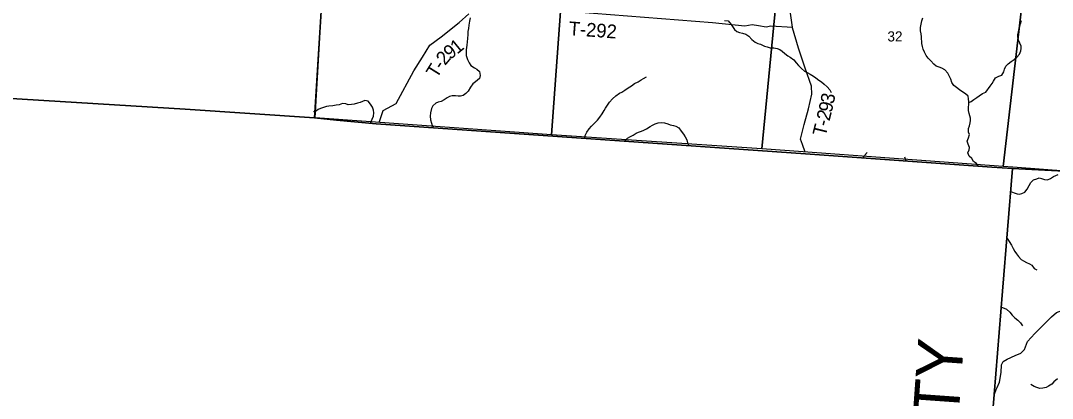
# Model space of a CAD drawing. Extents: x 1715311 to 2083412, y 146837 to 553079.
# Drawn here: x 1874751 to 1897277, y 339371 to 347616 of the extents above; entities that cross this region are included whole.
import ezdxf

# ---------------------------------------------------------------- set-up
doc = ezdxf.new("R2010")
doc.units = 0
for name, color, linetype in [('GM_X_Adjacent_County', 7, 'Continuous'), ('GM_X_Adjacent_County_Text', 7, 'Continuous'), ('GM_X_County', 7, 'Continuous'), ('GM_X_County_Road', 7, 'Continuous'), ('GM_X_Major_River', 7, 'Continuous'), ('GM_X_Minor_River', 7, 'Continuous'), ('GM_X_Section', 7, 'Continuous'), ('GM_X_Section_Text', 7, 'Continuous'), ('GM_X_Township', 7, 'Continuous'), ('GM_X_Township_Road', 7, 'Continuous'), ('GM_X_Township_Road_Text', 7, 'Continuous')]:
    doc.layers.add(name, color=color, linetype=linetype)

msp = doc.modelspace()

# ---------------------------------------------------------------- linework, layer by layer
at = {"layer": 'GM_X_Adjacent_County'}
for points in [[(1882647, 364366), (1882063, 357591), (1881945, 356213), (1881936, 356109), (1881811, 354649), (1881526, 351343), (1881415, 350049), (1881322, 347941), (1881166, 345493), (1878346, 345682), (1874430, 345924)], [(1874430, 345924), (1878346, 345682), (1881166, 345493), (1881644, 345443), (1882510, 345364), (1891886, 344709), (1895952, 344420), (1896407, 344385), (1896189, 341713), (1896008, 339458), (1895779, 336659)]]:
    msp.add_lwpolyline(points, dxfattribs=at)
at = {"layer": 'GM_X_County'}
msp.add_lwpolyline([(1895779, 336659), (1896008, 339458), (1896189, 341713), (1896407, 344385), (1895952, 344420), (1891886, 344709), (1882510, 345364), (1881644, 345443), (1881166, 345493), (1881322, 347941), (1881415, 350049), (1881526, 351343), (1881811, 354649), (1881936, 356109), (1881945, 356213), (1882063, 357591), (1882647, 364366)], dxfattribs=at)
at = {"layer": 'GM_X_County_Road'}
for points in [[(1896069, 339606), (1896121, 339723), (1896156, 339934), (1896165, 340102), (1896200, 340172), (1896288, 340225), (1896464, 340304), (1896587, 340357), (1896666, 340436), (1896737, 340612), (1896895, 340788), (1897071, 340963), (1897256, 341148), (1897370, 341245), (1897485, 341289), (1897810, 341298), (1898567, 341254), (1899198, 341237)], [(1895777, 336640), (1895779, 336659), (1896008, 339458), (1896011, 339465), (1896051, 339565), (1896068, 339605), (1896069, 339606)]]:
    msp.add_lwpolyline(points, dxfattribs=at)
at = {"layer": 'GM_X_Major_River'}
msp.add_lwpolyline([(1884565, 347678), (1884550, 347604), (1884538, 347514), (1884529, 347444), (1884518, 347376), (1884512, 347310), (1884505, 347226), (1884501, 347156), (1884494, 347084), (1884488, 347028), (1884477, 346976), (1884477, 346921), (1884480, 346853), (1884505, 346767), (1884541, 346693), (1884582, 346634), (1884658, 346584), (1884711, 346553), (1884771, 346505), (1884786, 346422), (1884770, 346350), (1884685, 346279), (1884621, 346235), (1884574, 346162), (1884522, 346078), (1884471, 346022), (1884409, 345981), (1884357, 345969), (1884305, 345970), (1884245, 345974), (1884175, 345973), (1884115, 345959), (1884065, 345932), (1884000, 345888), (1883934, 345851), (1883866, 345837), (1883816, 345816), (1883747, 345754), (1883721, 345698), (1883698, 345600), (1883692, 345528), (1883701, 345454), (1883718, 345380), (1883736, 345330), (1883758, 345292)], dxfattribs=at)
at = {"layer": 'GM_X_Minor_River'}
for points in [[(1890117, 347616), (1890197, 347610), (1890261, 347535), (1890309, 347469), (1890338, 347419), (1890390, 347379), (1890444, 347357), (1890514, 347340), (1890582, 347322), (1890652, 347274), (1890713, 347205), (1890785, 347147), (1890845, 347119), (1890907, 347099), (1890991, 347062), (1891051, 347044), (1891118, 347024), (1891194, 347020), (1891268, 347005), (1891326, 346987), (1891378, 346953), (1891436, 346899), (1891498, 346850), (1891549, 346820), (1891629, 346758), (1891681, 346696), (1891737, 346639), (1891796, 346569), (1891866, 346513), (1891922, 346483), (1891986, 346446), (1892058, 346406), (1892113, 346364), (1892175, 346316), (1892235, 346279), (1892297, 346229), (1892360, 346171), (1892416, 346103), (1892448, 346048)], [(1895662, 344441), (1895618, 344498), (1895552, 344542), (1895520, 344609), (1895461, 344659), (1895433, 344731), (1895461, 344797), (1895467, 344847), (1895438, 344921), (1895420, 344987), (1895442, 345057), (1895464, 345131), (1895445, 345183), (1895443, 345263), (1895467, 345321), (1895479, 345387), (1895489, 345437), (1895492, 345489), (1895460, 345590), (1895448, 345658), (1895448, 345724), (1895455, 345786), (1895455, 345844), (1895449, 345912), (1895435, 345964), (1895382, 346018), (1895320, 346058), (1895246, 346105), (1895180, 346153), (1895128, 346197), (1895085, 346267), (1895059, 346340), (1895033, 346400), (1894993, 346468), (1894930, 346540), (1894864, 346580), (1894806, 346599), (1894740, 346621), (1894688, 346669), (1894621, 346737), (1894563, 346800), (1894523, 346858), (1894484, 346930), (1894454, 346992), (1894442, 347052), (1894430, 347116), (1894419, 347261), (1894411, 347325), (1894401, 347395), (1894399, 347467), (1894412, 347537), (1894430, 347609), (1894448, 347675)], [(1895455, 345828), (1895507, 345854), (1895563, 345895), (1895631, 345939), (1895681, 345973), (1895751, 346025), (1895821, 346051), (1895922, 346182), (1895964, 346244), (1895994, 346298), (1896032, 346370), (1896110, 346406), (1896170, 346424), (1896215, 346498), (1896235, 346554), (1896261, 346620), (1896313, 346675), (1896377, 346721), (1896441, 346771), (1896498, 346821), (1896556, 346887), (1896588, 346957), (1896598, 347009), (1896594, 347059), (1896563, 347125), (1896535, 347191), (1896521, 347259), (1896525, 347315), (1896535, 347365), (1896548, 347415), (1896568, 347487), (1896582, 347547), (1896600, 347619)], [(1887072, 345056), (1887079, 345111), (1887113, 345180), (1887167, 345256), (1887215, 345314), (1887280, 345380), (1887342, 345446), (1887398, 345510), (1887446, 345580), (1887488, 345654), (1887519, 345705), (1887561, 345773), (1887607, 345837), (1887671, 345909), (1887747, 345975), (1887827, 346031), (1887878, 346058), (1887944, 346098), (1888018, 346150), (1888090, 346194), (1888156, 346246), (1888230, 346281), (1888296, 346325), (1888348, 346351), (1888418, 346389)], [(1882397, 345390), (1882426, 345467), (1882452, 345533), (1882460, 345605), (1882452, 345659), (1882431, 345725), (1882393, 345795), (1882335, 345856), (1882267, 345870), (1882213, 345850), (1882161, 345832), (1882103, 345812), (1882031, 345795), (1881977, 345785), (1881905, 345779), (1881849, 345797), (1881781, 345805), (1881707, 345778), (1881639, 345774), (1881565, 345756), (1881483, 345746), (1881429, 345743), (1881301, 345699), (1881249, 345677), (1881185, 345629), (1881148, 345623)], [(1887941, 344993), (1888000, 345049), (1888054, 345081), (1888126, 345115), (1888192, 345159), (1888242, 345178), (1888308, 345204), (1888358, 345224), (1888414, 345254), (1888494, 345302), (1888548, 345334), (1888601, 345365), (1888671, 345383), (1888740, 345393), (1888810, 345387), (1888880, 345364), (1888934, 345344), (1889002, 345324), (1889054, 345310), (1889124, 345276), (1889169, 345205), (1889221, 345135), (1889257, 345083), (1889293, 345011), (1889312, 344947), (1889343, 344893)], [(1893143, 344621), (1893176, 344675), (1893233, 344739)], [(1894082, 344554), (1894054, 344634)], [(1896370, 343883), (1896439, 343859), (1896509, 343833), (1896561, 343828), (1896611, 343842), (1896673, 343874), (1896723, 343940), (1896767, 344016), (1896804, 344082), (1896868, 344142), (1896936, 344165), (1896988, 344181), (1897042, 344169), (1897108, 344145), (1897170, 344143), (1897234, 344172), (1897300, 344216), (1897400, 344255)], [(1896287, 342861), (1896331, 342793), (1896385, 342714), (1896419, 342644), (1896458, 342576), (1896494, 342524), (1896538, 342464), (1896592, 342403), (1896646, 342373), (1896713, 342335), (1896775, 342307), (1896827, 342275), (1896879, 342208), (1896941, 342174)], [(1896165, 341363), (1896226, 341340), (1896278, 341318), (1896348, 341254), (1896398, 341185), (1896459, 341129), (1896525, 341077), (1896579, 341017), (1896623, 340951)], [(1897387, 339797), (1897308, 339729), (1897266, 339678), (1897193, 339636), (1897141, 339608), (1897071, 339592), (1897001, 339584), (1896936, 339609), (1896882, 339629), (1896810, 339673)]]:
    msp.add_lwpolyline(points, dxfattribs=at)
at = {"layer": 'GM_X_Section'}
for points in [[(1886739, 350610), (1891454, 350238), (1890933, 344817), (1886342, 345121), (1886716, 350318)], [(1881476, 350500), (1886716, 350318), (1886342, 345121), (1881181, 345492)], [(1891454, 350238), (1896827, 349829), (1896200, 344435), (1891837, 344752), (1890933, 344817)], [(1896827, 349829), (1902187, 349333), (1901774, 344007), (1896416, 344416), (1896200, 344435)]]:
    msp.add_lwpolyline(points, close=True, dxfattribs=at)
at = {"layer": 'GM_X_Township'}
for points in [[(1897396, 344334), (1896407, 344385), (1895952, 344420), (1891886, 344709), (1882510, 345364), (1881644, 345443), (1881166, 345493), (1881322, 347941), (1881415, 350049), (1881526, 351343), (1881811, 354649), (1881936, 356109), (1881945, 356213), (1882063, 357591), (1882647, 364366)], [(1895779, 336659), (1896008, 339458), (1896189, 341713), (1896407, 344385), (1897396, 344334), (1900188, 344104), (1902260, 343934), (1905609, 343672), (1907016, 343561), (1908092, 343486), (1912506, 343119), (1915843, 342855), (1917981, 342685), (1917863, 341233), (1917738, 339604), (1917501, 336918)]]:
    msp.add_lwpolyline(points, dxfattribs=at)
at = {"layer": 'GM_X_Township_Road'}
for points in [[(1885892, 348446), (1886517, 347840), (1889858, 347578), (1890563, 347504), (1890721, 347531), (1890861, 347509), (1891027, 347482), (1891133, 347501), (1891602, 347470)], [(1891883, 344743), (1891818, 344910), (1891778, 345029), (1891861, 345349), (1891949, 345693), (1892025, 346011), (1892020, 346183), (1891880, 346577), (1891732, 347016), (1891604, 347457), (1891602, 347470), (1891519, 348092)], [(1882575, 345394), (1882665, 345656), (1882948, 345805), (1883334, 346519), (1883522, 346818), (1883683, 347078), (1883935, 347263), (1884323, 347576), (1884536, 347763)]]:
    msp.add_lwpolyline(points, dxfattribs=at)

# ---------------------------------------------------------------- texts
at = {"layer": 'GM_X_Adjacent_County_Text'}
msp.add_text('SCIOTO COUNTY', height=1000, rotation=85.9252, dxfattribs=at).set_placement((1894557, 329522))
at = {"layer": 'GM_X_Section_Text'}
msp.add_text('32', height=221, rotation=0, dxfattribs=at).set_placement((1893676, 347161))
at = {"layer": 'GM_X_Township_Road_Text'}
for s, rotation, p in [('T-292', 355.7731, (1886710, 347301)), ('1', 39.2238, (1884282, 346873)), ('2', 49.8299, (1884018, 346625)), ('9', 36.9219, (1884124, 346754)), ('T', 58.1086, (1883838, 346340)), ('-', 56.6672, (1883956, 346529)), ('3', 78.487, (1892500, 345783)), ('9', 76.8704, (1892456, 345594)), ('2', 76.2614, (1892411, 345411)), ('T', 76.0459, (1892327, 345072)), ('-', 76.0728, (1892381, 345290))]:
    msp.add_text(s, height=300, rotation=rotation, dxfattribs=at).set_placement(p)

doc.saveas('drawing.dxf')
